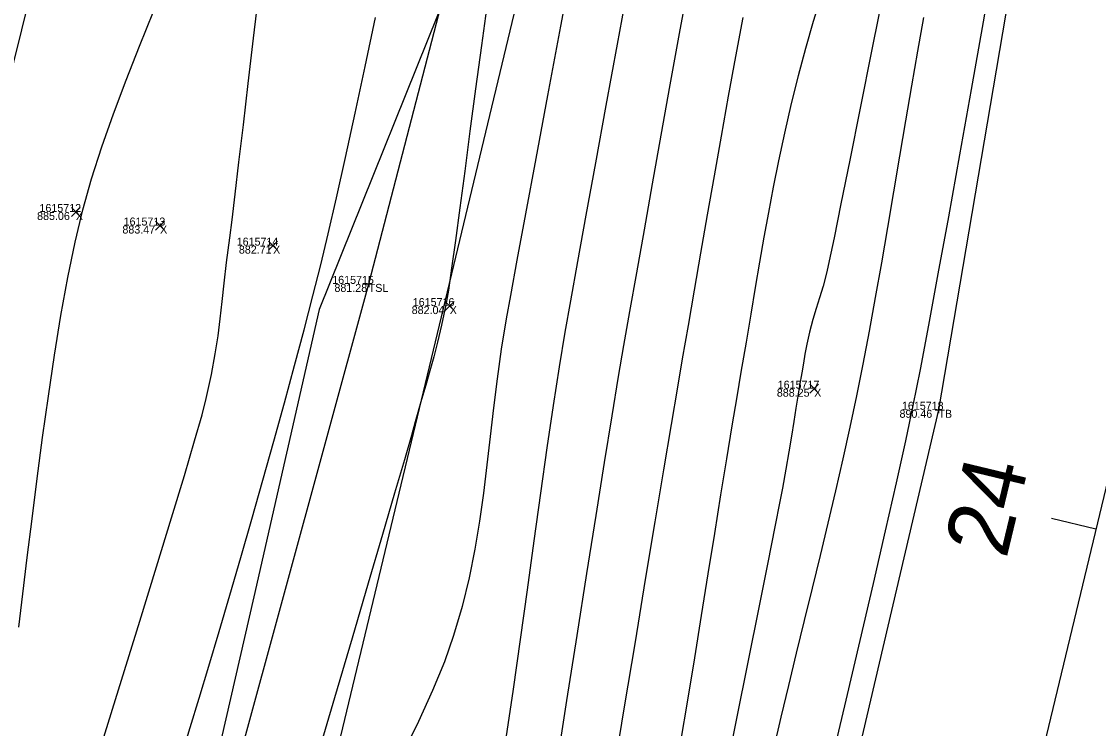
# Model space of a CAD drawing. Extents: x 1957117 to 1971063, y 701601 to 715861.
# Drawn here: x 1962877.57 to 1962924.68, y 704372.87 to 704403.79 of the extents above; entities that cross this region are included whole.
import ezdxf

# ---------------------------------------------------------------- set-up
doc = ezdxf.new("R2010")
doc.units = 0
for name, color, linetype in [('AP_X_Lights', 7, 'Continuous'), ('DT_X_Break_Line', 7, 'Continuous'), ('DT_X_Contour_Major', 7, 'Continuous'), ('DT_X_Contour_Minor', 7, 'Continuous'), ('DT_X_TIN_Hull', 7, 'Continuous'), ('GE_X_CL_20', 7, 'Continuous'), ('HY_X_Water_Edge', 7, 'Continuous'), ('PV_P_Drive', 7, 'Continuous'), ('PV_P_Shoulder', 7, 'Continuous'), ('RS_Raster1', 7, 'Continuous'), ('RW_X_Esmt_RR', 7, 'Continuous'), ('SC_Scratch1', 7, 'Continuous'), ('VG_X_Tree_Line_Rt', 7, 'Continuous')]:
    doc.layers.add(name, color=color, linetype=linetype)

msp = doc.modelspace()

# ---------------------------------------------------------------- linework, layer by layer
at = {"layer": 'AP_X_Lights'}
for p, q in [((1962879.752, 704395.268), (1962880.14, 704395.658)), ((1962879.752, 704395.658), (1962880.14, 704395.268)), ((1962883.436, 704394.675), (1962883.824, 704395.065)), ((1962883.436, 704395.065), (1962883.824, 704394.675)), ((1962888.38, 704393.796), (1962888.768, 704394.186)), ((1962888.38, 704394.186), (1962888.768, 704393.796)), ((1962896.107, 704391.153), (1962896.495, 704391.543)), ((1962896.107, 704391.543), (1962896.495, 704391.153)), ((1962912.05, 704387.538), (1962912.438, 704387.928)), ((1962912.05, 704387.928), (1962912.438, 704387.538))]:
    msp.add_line(p, q, dxfattribs=at)
at = {"layer": 'DT_X_Break_Line'}
for points in [[(1962854.549, 704243.654), (1962868.069, 704295.231), (1962879.669, 704344.313), (1962892.757, 704392.318), (1962905.964, 704443.142), (1962917.718, 704492.375), (1962926.962, 704538.336), (1962936.778, 704587.265), (1962949.215, 704630.669), (1962963.968, 704683.754), (1962972.038, 704733.348), (1962988.206, 704780.999), (1962994.689, 704830.943), (1963004.932, 704879.138), (1963021.822, 704927.498), (1963031.944, 704976.286), (1963045.21, 705027.355), (1963059.618, 705072.384), (1963067.267, 705121.949)], [(1963081.686, 705067.168), (1963070.617, 705018.992), (1963060.629, 704969.66), (1963044.793, 704921.859), (1963033.624, 704869.219), (1963022.038, 704824.561), (1963012.554, 704778.141), (1962998.858, 704727.004), (1962987.967, 704677.611), (1962975.675, 704626.305), (1962966.447, 704580.213), (1962950.262, 704533.092), (1962939.515, 704481.257), (1962926.044, 704436.037), (1962917.68, 704386.811), (1962906.11, 704337.415), (1962892.064, 704289.931), (1962881.011, 704234.451)]]:
    msp.add_lwpolyline(points, dxfattribs=at)
at = {"layer": 'DT_X_Contour_Major'}
for points in [[(1962920.16, 704406.805), (1962919.631, 704403.784), (1962919.108, 704400.818), (1962918.6, 704397.957), (1962918.114, 704395.252), (1962917.659, 704392.753), (1962917.243, 704390.511), (1962916.874, 704388.577), (1962916.559, 704387.001), (1962916.232, 704385.458), (1962915.826, 704383.616), (1962915.352, 704381.518), (1962914.821, 704379.205), (1962914.243, 704376.72), (1962913.629, 704374.104), (1962912.99, 704371.4)], [(1962920.16, 704406.805), (1962919.631, 704403.784), (1962919.108, 704400.818), (1962918.6, 704397.957), (1962918.114, 704395.252), (1962917.659, 704392.753), (1962917.243, 704390.511), (1962916.874, 704388.577), (1962916.559, 704387.001), (1962916.232, 704385.458), (1962915.826, 704383.616), (1962915.352, 704381.518), (1962914.821, 704379.205), (1962914.243, 704376.72), (1962913.629, 704374.104), (1962912.99, 704371.4)], [(1962906.755, 704405.541), (1962906.342, 704403.278), (1962905.935, 704401.028), (1962905.539, 704398.823), (1962905.16, 704396.697), (1962904.801, 704394.681), (1962904.47, 704392.808), (1962904.17, 704391.112), (1962903.907, 704389.623), (1962903.674, 704388.268), (1962903.39, 704386.546), (1962903.059, 704384.505), (1962902.69, 704382.192), (1962902.288, 704379.655), (1962901.86, 704376.94), (1962901.412, 704374.095), (1962900.95, 704371.167)], [(1962906.755, 704405.541), (1962906.342, 704403.278), (1962905.935, 704401.028), (1962905.539, 704398.823), (1962905.16, 704396.697), (1962904.801, 704394.681), (1962904.47, 704392.808), (1962904.17, 704391.112), (1962903.907, 704389.623), (1962903.674, 704388.268), (1962903.39, 704386.546), (1962903.059, 704384.505), (1962902.69, 704382.192), (1962902.288, 704379.655), (1962901.86, 704376.94), (1962901.412, 704374.095), (1962900.95, 704371.167)]]:
    msp.add_lwpolyline(points, dxfattribs=at)
at = {"layer": 'DT_X_Contour_Minor'}
for points in [[(1962901.755, 704406.843), (1962901.147, 704403.592), (1962900.579, 704400.555), (1962900.065, 704397.796), (1962899.615, 704395.377), (1962899.242, 704393.361), (1962898.957, 704391.81), (1962898.773, 704390.788), (1962898.557, 704389.462), (1962898.376, 704388.167), (1962898.218, 704386.895), (1962898.073, 704385.642), (1962897.929, 704384.402), (1962897.776, 704383.17), (1962897.601, 704381.94), (1962897.395, 704380.708), (1962897.145, 704379.466), (1962896.841, 704378.21), (1962896.472, 704376.935), (1962896.065, 704375.786), (1962895.544, 704374.527), (1962894.929, 704373.177), (1962894.238, 704371.756)], [(1962901.755, 704406.843), (1962901.147, 704403.592), (1962900.579, 704400.555), (1962900.065, 704397.796), (1962899.615, 704395.377), (1962899.242, 704393.361), (1962898.957, 704391.81), (1962898.773, 704390.788), (1962898.557, 704389.462), (1962898.376, 704388.167), (1962898.218, 704386.895), (1962898.073, 704385.642), (1962897.929, 704384.402), (1962897.776, 704383.17), (1962897.601, 704381.94), (1962897.395, 704380.708), (1962897.145, 704379.466), (1962896.841, 704378.21), (1962896.472, 704376.935), (1962896.065, 704375.786), (1962895.544, 704374.527), (1962894.929, 704373.177), (1962894.238, 704371.756)], [(1962904.133, 704405.586), (1962903.621, 704402.798), (1962903.133, 704400.126), (1962902.676, 704397.62), (1962902.259, 704395.326), (1962901.892, 704393.294), (1962901.583, 704391.571), (1962901.34, 704390.205), (1962901.087, 704388.696), (1962900.825, 704386.997), (1962900.555, 704385.14), (1962900.275, 704383.157), (1962899.987, 704381.079), (1962899.691, 704378.937), (1962899.385, 704376.763), (1962899.072, 704374.588), (1962898.75, 704372.443)], [(1962904.133, 704405.586), (1962903.621, 704402.798), (1962903.133, 704400.126), (1962902.676, 704397.62), (1962902.259, 704395.326), (1962901.892, 704393.294), (1962901.583, 704391.571), (1962901.34, 704390.205), (1962901.087, 704388.696), (1962900.825, 704386.997), (1962900.555, 704385.14), (1962900.275, 704383.157), (1962899.987, 704381.079), (1962899.691, 704378.937), (1962899.385, 704376.763), (1962899.072, 704374.588), (1962898.75, 704372.443)], [(1962881.102, 704372.255), (1962881.948, 704374.981), (1962882.746, 704377.558), (1962883.479, 704379.939), (1962884.133, 704382.079), (1962884.692, 704383.932), (1962885.142, 704385.451), (1962885.466, 704386.589), (1962885.65, 704387.302), (1962885.874, 704388.357), (1962886.04, 704389.255), (1962886.164, 704390.05), (1962886.26, 704390.794), (1962886.344, 704391.542), (1962886.431, 704392.344), (1962886.536, 704393.256), (1962886.675, 704394.329), (1962886.778, 704395.127), (1962886.915, 704396.245), (1962887.082, 704397.64), (1962887.274, 704399.269), (1962887.488, 704401.09), (1962887.721, 704403.061), (1962887.968, 704405.138)], [(1962881.102, 704372.255), (1962881.948, 704374.981), (1962882.746, 704377.558), (1962883.479, 704379.939), (1962884.133, 704382.079), (1962884.692, 704383.932), (1962885.142, 704385.451), (1962885.466, 704386.589), (1962885.65, 704387.302), (1962885.874, 704388.357), (1962886.04, 704389.255), (1962886.164, 704390.05), (1962886.26, 704390.794), (1962886.344, 704391.542), (1962886.431, 704392.344), (1962886.536, 704393.256), (1962886.675, 704394.329), (1962886.778, 704395.127), (1962886.915, 704396.245), (1962887.082, 704397.64), (1962887.274, 704399.269), (1962887.488, 704401.09), (1962887.721, 704403.061), (1962887.968, 704405.138)], [(1962915.332, 704405.395), (1962914.768, 704402.578), (1962914.253, 704400.005), (1962913.797, 704397.735), (1962913.413, 704395.825), (1962913.112, 704394.335), (1962912.904, 704393.324), (1962912.802, 704392.849), (1962912.635, 704392.22), (1962912.48, 704391.706), (1962912.333, 704391.243), (1962912.189, 704390.767), (1962912.045, 704390.213), (1962911.924, 704389.676), (1962911.839, 704389.247), (1962911.771, 704388.853), (1962911.7, 704388.421), (1962911.607, 704387.877), (1962911.528, 704387.406), (1962911.444, 704386.88), (1962911.354, 704386.3), (1962911.253, 704385.661), (1962911.139, 704384.965), (1962911.01, 704384.207), (1962910.862, 704383.388), (1962910.747, 704382.797), (1962910.529, 704381.691), (1962910.217, 704380.125), (1962909.822, 704378.156), (1962909.357, 704375.839), (1962908.831, 704373.232), (1962908.257, 704370.39)], [(1962915.332, 704405.395), (1962914.768, 704402.578), (1962914.253, 704400.005), (1962913.797, 704397.735), (1962913.413, 704395.825), (1962913.112, 704394.335), (1962912.904, 704393.324), (1962912.802, 704392.849), (1962912.635, 704392.22), (1962912.48, 704391.706), (1962912.333, 704391.243), (1962912.189, 704390.767), (1962912.045, 704390.213), (1962911.924, 704389.676), (1962911.839, 704389.247), (1962911.771, 704388.853), (1962911.7, 704388.421), (1962911.607, 704387.877), (1962911.528, 704387.406), (1962911.444, 704386.88), (1962911.354, 704386.3), (1962911.253, 704385.661), (1962911.139, 704384.965), (1962911.01, 704384.207), (1962910.862, 704383.388), (1962910.747, 704382.797), (1962910.529, 704381.691), (1962910.217, 704380.125), (1962909.822, 704378.156), (1962909.357, 704375.839), (1962908.831, 704373.232), (1962908.257, 704370.39)], [(1962897.949, 704404.674), (1962897.684, 704402.751), (1962897.429, 704400.847), (1962897.185, 704399.001), (1962896.956, 704397.254), (1962896.745, 704395.645), (1962896.553, 704394.215), (1962896.385, 704393.004), (1962896.242, 704392.05), (1962896.127, 704391.396), (1962895.939, 704390.508), (1962895.768, 704389.773), (1962895.603, 704389.131), (1962895.434, 704388.521), (1962895.249, 704387.882), (1962895.04, 704387.156), (1962894.794, 704386.281), (1962894.624, 704385.681), (1962894.318, 704384.628), (1962893.891, 704383.168), (1962893.358, 704381.35), (1962892.732, 704379.221), (1962892.029, 704376.827), (1962891.262, 704374.217), (1962890.446, 704371.437)], [(1962897.949, 704404.674), (1962897.684, 704402.751), (1962897.429, 704400.847), (1962897.185, 704399.001), (1962896.956, 704397.254), (1962896.745, 704395.645), (1962896.553, 704394.215), (1962896.385, 704393.004), (1962896.242, 704392.05), (1962896.127, 704391.396), (1962895.939, 704390.508), (1962895.768, 704389.773), (1962895.603, 704389.131), (1962895.434, 704388.521), (1962895.249, 704387.882), (1962895.04, 704387.156), (1962894.794, 704386.281), (1962894.624, 704385.681), (1962894.318, 704384.628), (1962893.891, 704383.168), (1962893.358, 704381.35), (1962892.732, 704379.221), (1962892.029, 704376.827), (1962891.262, 704374.217), (1962890.446, 704371.437)], [(1962912.558, 704404.965), (1962912.206, 704403.793), (1962911.866, 704402.614), (1962911.544, 704401.422), (1962911.242, 704400.212), (1962910.945, 704398.916), (1962910.683, 704397.704), (1962910.451, 704396.555), (1962910.24, 704395.446), (1962910.044, 704394.357), (1962909.857, 704393.267), (1962909.669, 704392.153), (1962909.476, 704390.995), (1962909.268, 704389.771), (1962909.041, 704388.459), (1962908.854, 704387.38), (1962908.641, 704386.108), (1962908.406, 704384.669), (1962908.15, 704383.092), (1962907.879, 704381.405), (1962907.595, 704379.636), (1962907.302, 704377.812), (1962907.004, 704375.962), (1962906.703, 704374.113), (1962906.403, 704372.294)], [(1962912.558, 704404.965), (1962912.206, 704403.793), (1962911.866, 704402.614), (1962911.544, 704401.422), (1962911.242, 704400.212), (1962910.945, 704398.916), (1962910.683, 704397.704), (1962910.451, 704396.555), (1962910.24, 704395.446), (1962910.044, 704394.357), (1962909.857, 704393.267), (1962909.669, 704392.153), (1962909.476, 704390.995), (1962909.268, 704389.771), (1962909.041, 704388.459), (1962908.854, 704387.38), (1962908.641, 704386.108), (1962908.406, 704384.669), (1962908.15, 704383.092), (1962907.879, 704381.405), (1962907.595, 704379.636), (1962907.302, 704377.812), (1962907.004, 704375.962), (1962906.703, 704374.113), (1962906.403, 704372.294)], [(1962877.445, 704377.303), (1962877.626, 704378.761), (1962877.821, 704380.349), (1962878.029, 704382.039), (1962878.252, 704383.799), (1962878.49, 704385.599), (1962878.743, 704387.409), (1962879.011, 704389.2), (1962879.295, 704390.94), (1962879.595, 704392.6), (1962879.913, 704394.149), (1962880.247, 704395.557), (1962880.628, 704396.912), (1962881.08, 704398.314), (1962881.59, 704399.756), (1962882.146, 704401.228), (1962882.736, 704402.721), (1962883.348, 704404.227)], [(1962877.445, 704377.303), (1962877.626, 704378.761), (1962877.821, 704380.349), (1962878.029, 704382.039), (1962878.252, 704383.799), (1962878.49, 704385.599), (1962878.743, 704387.409), (1962879.011, 704389.2), (1962879.295, 704390.94), (1962879.595, 704392.6), (1962879.913, 704394.149), (1962880.247, 704395.557), (1962880.628, 704396.912), (1962881.08, 704398.314), (1962881.59, 704399.756), (1962882.146, 704401.228), (1962882.736, 704402.721), (1962883.348, 704404.227)], [(1962884.59, 704371.766), (1962884.947, 704372.906), (1962885.341, 704374.19), (1962885.766, 704375.596), (1962886.215, 704377.105), (1962886.682, 704378.695), (1962887.161, 704380.344), (1962887.645, 704382.031), (1962888.128, 704383.737), (1962888.604, 704385.439), (1962889.066, 704387.116), (1962889.509, 704388.748), (1962889.926, 704390.313), (1962890.311, 704391.79), (1962890.657, 704393.158), (1962890.981, 704394.504), (1962891.343, 704396.081), (1962891.737, 704397.851), (1962892.157, 704399.78), (1962892.595, 704401.831), (1962893.047, 704403.971)], [(1962884.59, 704371.766), (1962884.947, 704372.906), (1962885.341, 704374.19), (1962885.766, 704375.596), (1962886.215, 704377.105), (1962886.682, 704378.695), (1962887.161, 704380.344), (1962887.645, 704382.031), (1962888.128, 704383.737), (1962888.604, 704385.439), (1962889.066, 704387.116), (1962889.509, 704388.748), (1962889.926, 704390.313), (1962890.311, 704391.79), (1962890.657, 704393.158), (1962890.981, 704394.504), (1962891.343, 704396.081), (1962891.737, 704397.851), (1962892.157, 704399.78), (1962892.595, 704401.831), (1962893.047, 704403.971)], [(1962909.126, 704403.968), (1962908.803, 704402.261), (1962908.484, 704400.527), (1962908.171, 704398.783), (1962907.864, 704397.047), (1962907.565, 704395.334), (1962907.276, 704393.66), (1962906.997, 704392.042), (1962906.729, 704390.497), (1962906.474, 704389.041), (1962906.26, 704387.807), (1962905.983, 704386.172), (1962905.651, 704384.187), (1962905.272, 704381.906), (1962904.855, 704379.382), (1962904.407, 704376.666), (1962903.938, 704373.812), (1962903.456, 704370.872)], [(1962909.126, 704403.968), (1962908.803, 704402.261), (1962908.484, 704400.527), (1962908.171, 704398.783), (1962907.864, 704397.047), (1962907.565, 704395.334), (1962907.276, 704393.66), (1962906.997, 704392.042), (1962906.729, 704390.497), (1962906.474, 704389.041), (1962906.26, 704387.807), (1962905.983, 704386.172), (1962905.651, 704384.187), (1962905.272, 704381.906), (1962904.855, 704379.382), (1962904.407, 704376.666), (1962903.938, 704373.812), (1962903.456, 704370.872)], [(1962917.024, 704403.966), (1962916.76, 704402.494), (1962916.498, 704400.986), (1962916.236, 704399.451), (1962915.974, 704397.899), (1962915.712, 704396.341), (1962915.449, 704394.787), (1962915.184, 704393.246), (1962914.916, 704391.729), (1962914.646, 704390.245), (1962914.373, 704388.805), (1962914.096, 704387.419), (1962913.807, 704386.052), (1962913.5, 704384.666), (1962913.178, 704383.265), (1962912.844, 704381.853), (1962912.502, 704380.433), (1962912.156, 704379.009), (1962911.807, 704377.586), (1962911.461, 704376.167), (1962911.119, 704374.757), (1962910.786, 704373.358), (1962910.464, 704371.975)], [(1962917.024, 704403.966), (1962916.76, 704402.494), (1962916.498, 704400.986), (1962916.236, 704399.451), (1962915.974, 704397.899), (1962915.712, 704396.341), (1962915.449, 704394.787), (1962915.184, 704393.246), (1962914.916, 704391.729), (1962914.646, 704390.245), (1962914.373, 704388.805), (1962914.096, 704387.419), (1962913.807, 704386.052), (1962913.5, 704384.666), (1962913.178, 704383.265), (1962912.844, 704381.853), (1962912.502, 704380.433), (1962912.156, 704379.009), (1962911.807, 704377.586), (1962911.461, 704376.167), (1962911.119, 704374.757), (1962910.786, 704373.358), (1962910.464, 704371.975)]]:
    msp.add_lwpolyline(points, dxfattribs=at)
at = {"layer": 'DT_X_TIN_Hull'}
msp.add_lwpolyline([(1963062.2, 705175.46), (1963037.999, 705077.244), (1963026.56, 705028.621), (1963015.244, 704980.352), (1962992.578, 704882.771), (1962981.085, 704833.91), (1962969.384, 704785.804), (1962957.851, 704737.276), (1962945.67, 704688.173), (1962933.954, 704639.432), (1962922.363, 704591.169), (1962899.093, 704494.258), (1962887.945, 704444.945), (1962875.826, 704396.455), (1962864.548, 704347.909), (1962854.544, 704302.816), (1962839.463, 704247.251)], dxfattribs=at)
at = {"layer": 'GE_X_CL_20'}
msp.add_line((1962924.569, 704381.595), (1962922.624, 704382.062), dxfattribs=at)
msp.add_lwpolyline([(1963418.3, 706437.397), (1962895.621, 704261.062)], dxfattribs=at)
at = {"layer": 'HY_X_Water_Edge'}
msp.add_spline([(1963191.723, 701994.048), (1963062.047, 702441.167), (1962863.491, 703169.356), (1962827.53, 703438.691), (1962823.213, 703537.412), (1962817.962, 703593.874), (1962817.97, 703697.316), (1962828.582, 703804.235), (1962836.461, 703844.734), (1962850.687, 703896.004), (1962867.251, 703938.846), (1962873.848, 703992.355), (1962884.135, 704091.371), (1962891.241, 704140.854), (1962897.382, 704180.529), (1962905.467, 704230.979), (1962943.949, 704328.022), (1962948.537, 704378.842), (1962964.114, 704426.264), (1963004.885, 704570.73), (1963042.054, 704716.522), (1963062.038, 704814.417), (1963072.171, 704860.237), (1963090.023, 704956.798), (1963107.066, 705031.783), (1963133.773, 705105.742), (1963148.685, 705206.74), (1963175.48, 705301.059), (1963191.635, 705353.417), (1963210.988, 705447.286), (1963219.532, 705497.27), (1963230.124, 705549.475), (1963251.052, 705591.159), (1963275.289, 705693.429), (1963292.982, 705784.032), (1963302.841, 705839.645), (1963335.126, 705936.766), (1963359.752, 706046.75), (1963389.133, 706177.299), (1963417.827, 706273.456), (1963475.868, 706451.902), (1963533.782, 706640.53), (1963553.86, 706696.984), (1963580.184, 706715.425), (1963609.172, 706718.73), (1963617.062, 706714.691), (1963619.447, 706694.678), (1963564.282, 706533.07), (1963531.853, 706395.229), (1963434.4, 706006.96), (1963354.09, 705679.186), (1963237.513, 705206.07), (1963167.369, 704892.962), (1963059.145, 704434.176), (1962907.914, 703908.742), (1962877.458, 703703.326), (1962898.357, 703412.121), (1962942.65, 703052.267), (1963048.963, 702674.866), (1963191.468, 702189.666), (1963245.396, 702019.832)], degree=3, dxfattribs=at)
at = {"layer": 'PV_P_Drive'}
for p, q in [((1962892.611, 704392.318), (1962892.903, 704392.318)), ((1962892.757, 704392.464), (1962892.757, 704392.172)), ((1962892.757, 704392.318), (1962892.757, 704392.318)), ((1962917.534, 704386.811), (1962917.826, 704386.811)), ((1962917.68, 704386.957), (1962917.68, 704386.665)), ((1962917.68, 704386.811), (1962917.68, 704386.811))]:
    msp.add_line(p, q, dxfattribs=at)
at = {"layer": 'RW_X_Esmt_RR'}
msp.add_lwpolyline([(1962866.45, 704268.068), (1963123.345, 705337.727), (1963135.496, 705336.937), (1963400.797, 706441.601)], dxfattribs=at)
at = {"layer": 'VG_X_Tree_Line_Rt'}
msp.add_lwpolyline([(1962896.726, 704406.459), (1962890.596, 704391.197), (1962887.737, 704378.622), (1962883.607, 704360.65), (1962878.114, 704347.666), (1962876.518, 704338.397), (1962875.174, 704331.532), (1962875.083, 704325.504), (1962870.984, 704312.315), (1962869.275, 704304.568), (1962866.794, 704299.997), (1962862.288, 704297.127), (1962860.184, 704291.687), (1962865.692, 704286.944), (1962868.971, 704284.055), (1962868.665, 704277.293)], dxfattribs=at)

# ---------------------------------------------------------------- texts
at = {"layer": 'GE_X_CL_20'}
msp.add_text('24', height=2.8, rotation=76.4953, dxfattribs=at).set_placement((1962920.646, 704380.252))
at = {"layer": 'PV_P_Shoulder'}
for s, p in [('885.06', (1962878.251, 704395.113)), ('883.47', (1962881.982, 704394.52)), ('882.71', (1962887.077, 704393.641)), ('881.28', (1962891.258, 704391.968)), ('882.04', (1962894.637, 704390.998)), ('888.25', (1962910.61, 704387.383)), ('890.46', (1962915.977, 704386.461))]:
    msp.add_text(s, height=0.35, dxfattribs=at).set_placement(p)
at = {"layer": 'RS_Raster1'}
for s, p in [('1615712', (1962878.354, 704395.463)), ('1615713', (1962882.035, 704394.87)), ('1615714', (1962886.982, 704393.991)), ('1615715', (1962891.162, 704392.318)), ('1615716', (1962894.684, 704391.348)), ('1615717', (1962910.649, 704387.733)), ('1615718', (1962916.082, 704386.811))]:
    msp.add_text(s, height=0.35, dxfattribs=at).set_placement(p)
at = {"layer": 'SC_Scratch1'}
for s, p in [('X', (1962879.946, 704395.113)), ('X', (1962883.63, 704394.52)), ('X', (1962888.574, 704393.641)), ('TSL', (1962892.757, 704391.968)), ('X', (1962896.301, 704390.998)), ('X', (1962912.244, 704387.383)), ('TB', (1962917.68, 704386.461))]:
    msp.add_text(s, height=0.35, dxfattribs=at).set_placement(p)

doc.saveas('drawing.dxf')
